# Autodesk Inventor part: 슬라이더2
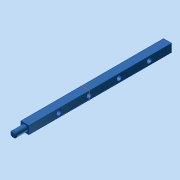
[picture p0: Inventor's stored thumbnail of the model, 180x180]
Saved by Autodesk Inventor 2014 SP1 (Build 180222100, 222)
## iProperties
Company: 한국ATC센터
Created: 2015-04
Part Number: 슬라이더2
Document SubType Name: Modeling
Designer: KYOUNG IL JANG
Density: 7.85 g/cm^3
Material: 강
Appearance: 하늘색 짙음
Author: KYOUNG IL JANG
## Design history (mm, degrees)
sketch "스케치3"
  geometry: L1 (4, 142)-(-4, 142); L2 (-4, 142)-(-4, 0); L3 (-4, 0)-(4, 0); L4 (4, 0)-(4, 142); 3 further points
  constraints: 8 end point, 2 coincident, 2 parallel, 1 horizontal, 1 midpoint, 1 perpendicular
  dimensions: "d5" = 8 distance of L1.start L1.end; "d6" = 142 distance of L1.end L2.end
extrude "돌출3" new body sketch "스케치3" stored distance "d7" = 8; taper "d8" = 0 deg
sketch "스케치4"
  geometry: L1 (8, 0)-(0, 0) reference; 3 further points
  constraints: 1 midpoint, 1 vertical alignment
  dimensions: "d9" = 30 distance of point (4, 30) point (4, 0)
hole "구멍1" sketch "스케치4" at (4, 30) diameter "d10" = 5; stored, may be unused: countersink angle "d14" = 90 deg, drill point angle "d16" = 118 deg; dims "d11" = 6, "d12" = 4, "d13" = 2, "d15" = 8
sketch "스케치5"
  geometry: C1 r 3 at (4, -4); 1 further point
  constraints: 1 centre point, 1 coincident
  dimensions: "d20" = 6 diameter of C1
extrude "돌출4" join sketch "스케치5" distance "d21" = 12; taper "d22" = 0 deg
chamfer "모따기1" distance "d23" = 1; stored, may be unused: second distance "d24" = 2, angle "d25" = 45 deg
node "작업 평면2"
  node "작업축1"
node "솔리드1"
pattern_linear "직사각형 패턴1" dims "d19" = 30
node "솔리드2"
other parameters: "d26" = 0
